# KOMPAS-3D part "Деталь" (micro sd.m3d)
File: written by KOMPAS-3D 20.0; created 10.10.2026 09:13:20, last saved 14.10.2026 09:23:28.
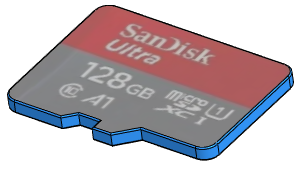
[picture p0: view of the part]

Document properties: Полное имя файла: D:\myProjects\Progect_esp32\box_compas\SD card\micro sd.m3d

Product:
- Part/product: Деталь
    Масса: 0.00121292

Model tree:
1. Эскиз:1
2. Элемент выдавливания:1
     Расстояние 1 = 1
3. Эскиз:2  (with: Элемент выдавливания:1)
4. Элемент выдавливания:2
     Расстояние 2 = 1
5. Фаска:1  (with: Элемент выдавливания:2)
     Угол = 45; Длина 1 = 1.6; Длина 2 = 1.6
6. Фаска:2  (with: Элемент выдавливания:2)
     Угол = 45; Длина 1 = 0.8; Длина 2 = 0.8
7. Скругление:1  (with: Элемент выдавливания:2, Элемент выдавливания:1)
     Радиус = 1
8. Скругление:2  (with: Элемент выдавливания:1)
     Радиус = 0.1

Referenced files in D:\myProjects\Progect_esp32\box_compas\: micro sd.png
